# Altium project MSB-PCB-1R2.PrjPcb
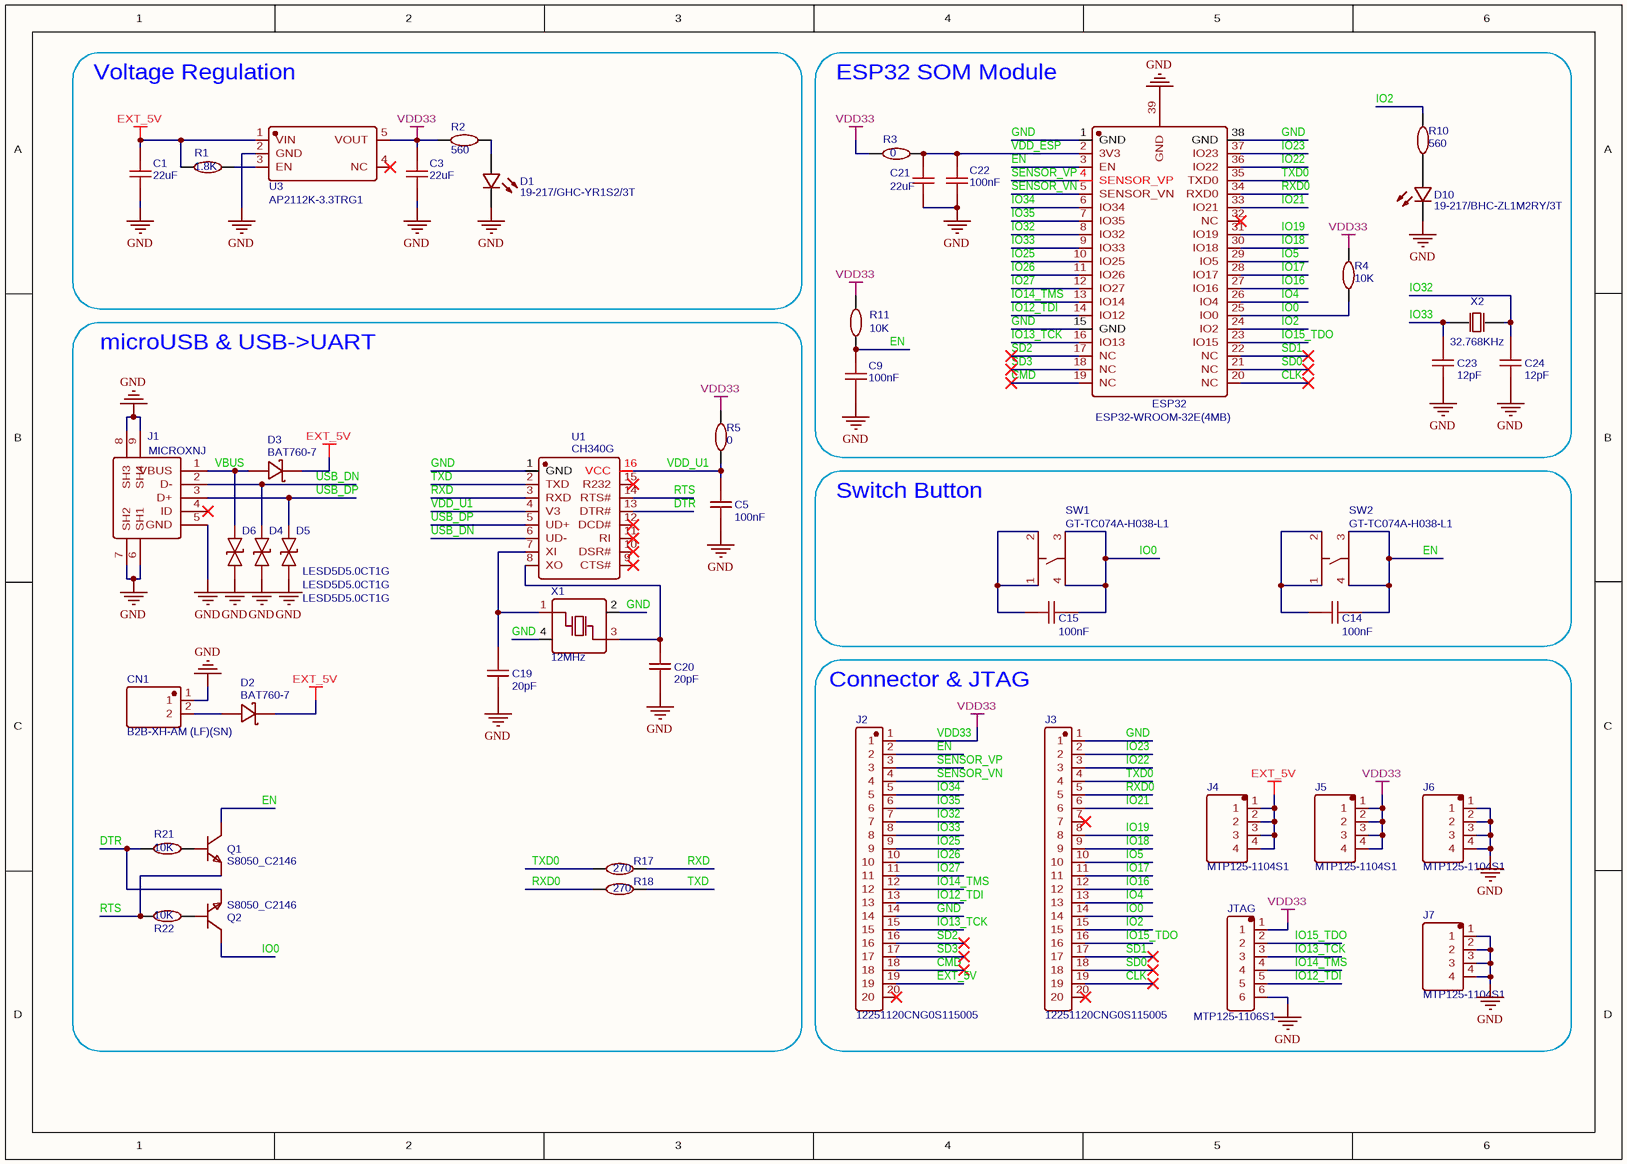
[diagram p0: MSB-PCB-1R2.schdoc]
PRJ_AssemblyVariantStatus: Prototype; PRJ_CompanySiteName: MakerSpace Bonn e.V.; PRJ_DeveloperDate: 15.06.2021; PRJ_DeveloperName: NEK; PRJ_Layouter: NEK; PRJ_PcbNumber: 01; PRJ_PcbVersion: 01; PRJ_SchematicMainTitle: 1rpc ESP32 Baseboard
1 sheet, 48 parts. Net scope: global (net labels, ports and power ports of the same name join across sheets).
Board file: MSB-PCB-1R2.PcbDoc

## Sheet MSB-PCB-1R2.schdoc
size 304 x 217 mm

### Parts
C1  22uF  [C0603]
C3  22uF  [C0603]
C5  100nF  [C0603]
C9  100nF  [C0603]
C14  100nF  [C0603]
C15  100nF  [C0603]
C19  20pF  [C0603]
C20  20pF  [C0603]
C21  22uF  [C0603]
C22  100nF  [C0603]
C23  12pF  [C0603]
C24  12pF  [C0603]
CN1  B2B-XH-AM (LF)(SN)  [CONN-TH_B2B-XH-AM-LF-SN]
D1  19-217/GHC-YR1S2/3T  [LED0603-R-RD]
D2  BAT760-7  [SOD-323_L1.8-W1.3-LS2.5-RD]
D3  BAT760-7  [SOD-323_L1.8-W1.3-LS2.5-RD]
D4  LESD5D5.0CT1G  [SOD-523_L1.2-W0.8-LS1.6-BI]
D5  LESD5D5.0CT1G  [SOD-523_L1.2-W0.8-LS1.6-BI]
D6  LESD5D5.0CT1G  [SOD-523_L1.2-W0.8-LS1.6-BI]
D10  19-217/BHC-ZL1M2RY/3T  [LED0603-R-RD]
ESP32  ESP32-WROOM-32E(4MB)  [WIFI-SMD_ESP32-WROOM-32E]
J1  MICROXNJ  [MICRO-USB-SMD_MICROXNJ]
J2  12251120CNG0S115005  [HDR-TH_19P-P2.54-V]
J3  12251120CNG0S115005  [HDR-TH_19P-P2.54-V]
J4  MTP125-1104S1  [HDR-TH_4P-P2.54-V]
J5  MTP125-1104S1  [HDR-TH_4P-P2.54-V]
J6  MTP125-1104S1  [HDR-TH_4P-P2.54-V]
J7  MTP125-1104S1  [HDR-TH_4P-P2.54-V]
JTAG  MTP125-1106S1  [HDR-TH_6P-P2.54-V]
Q1  S8050_C2146  [SOT-23-3_L3.0-W1.7-P0.95-LS2.9-BR]
Q2  S8050_C2146  [SOT-23-3_L3.0-W1.7-P0.95-LS2.9-BR]
R1  1.8K  [R0603]
R2  560  [R0603]
R3  0  [R0603]
R4  10K  [R0603]
R5  0  [R0603]
R10  560  [R0603]
R11  10K  [R0603]
R17  270  [R0603]
R18  270  [R0603]
R21  10K  [R0603]
R22  10K  [R0603]
SW1  GT-TC074A-H038-L1  [SW-SMD_4P-L4.5-W4.5-P3.00-LS7.0]
SW2  GT-TC074A-H038-L1  [SW-SMD_4P-L4.5-W4.5-P3.00-LS7.0]
U1  CH340G  [SOIC-16_L9.9-W3.9-P1.27-LS6.0-TL]
U3  AP2112K-3.3TRG1  [SOT-25-5_L3.0-W1.8-P0.95-LS3.0-BR]
X1  12MHz  [OSC-SMD_4P-L3.2-W2.5-BL]
X2  32.768KHz  [OSC-SMD_L3.2-W1.5]

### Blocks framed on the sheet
Voltage Regulation: C1 C3 D1 R1 R2 U3
ESP32 SOM Module: C9 C21-C24 D10 ESP32 R3 R4 R10 R11 X2
microUSB & USB->UART: C5 C19 C20 CN1 D2-D6 J1 Q1 Q2 R5 R17 R18 R21 R22 U1 X1
Switch Button: C14 C15 SW1 SW2
Connector & JTAG: J2-J7 JTAG

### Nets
EXT_5V: C1.2 D2.1 D3.1 J2.19 J4.1 J4.2 J4.3 J4.4 R1.1 U3.1(VIN)
GND: C1.1 C3.1 C5.2 C9.1 C19.1 C20.1 C21.1 C22.1 C23.1 C24.1 CN1.1 D1.2(C) D4.1 D5.1 D6.1 D10.2(C) ESP32.1(GND) ESP32.15(GND) ESP32.38(GND) ESP32.39(GND) J1.5(GND) J1.6(SH1) J1.7(SH2) J1.8(SH3) J1.9(SH4) J2.14 J3.1 J6.1 J6.2 J6.3 J6.4 J7.1 J7.2 J7.3 J7.4 JTAG.6 U1.1(GND) U3.2(GND) X1.2(GND) X1.4(GND)
VDD33: C3.2 J2.1 J5.1 J5.2 J5.3 J5.4 JTAG.1 R2.2 R3.1 R4.2 R5.2 R11.2 U3.5(VOUT)
CLK: ESP32.20(NC) J3.19
CMD: ESP32.19(NC) J2.18
DTR: Q2.2(E) R21.1 U1.13(DTR#)
EN: C9.2 C14.2 ESP32.3(EN) J2.2 Q1.3(C) R11.1 SW2.3 SW2.4
IO0: C15.2 ESP32.25(IO0) J3.14 Q2.3(C) R4.1 SW1.3 SW1.4
IO2: ESP32.24(IO2) J3.15 R10.2
IO4: ESP32.26(IO4) J3.13
IO5: ESP32.29(IO5) J3.10
IO12_TDI: ESP32.14(IO12) J2.13 JTAG.5
IO13_TCK: ESP32.16(IO13) J2.15 JTAG.3
IO14_TMS: ESP32.13(IO14) J2.12 JTAG.4
IO15_TDO: ESP32.23(IO15) J3.16 JTAG.2
IO16: ESP32.27(IO16) J3.12
IO17: ESP32.28(IO17) J3.11
IO18: ESP32.30(IO18) J3.9
IO19: ESP32.31(IO19) J3.8
IO21: ESP32.33(IO21) J3.6
IO22: ESP32.36(IO22) J3.3
IO23: ESP32.37(IO23) J3.2
IO25: ESP32.10(IO25) J2.9
IO26: ESP32.11(IO26) J2.10
IO27: ESP32.12(IO27) J2.11
IO32: C24.2 ESP32.8(IO32) J2.7 X2.2(OSC2)
IO33: C23.2 ESP32.9(IO33) J2.8 X2.1(OSC1)
IO34: ESP32.6(IO34) J2.5
IO35: ESP32.7(IO35) J2.6
RTS: Q1.2(E) R22.1 U1.14(RTS#)
RXD: R17.2 U1.3(RXD)
RXD0: ESP32.34(RXD0) J3.5 R18.1
SD0: ESP32.21(NC) J3.18
SD1: ESP32.22(NC) J3.17
SD2: ESP32.17(NC) J2.16
SD3: ESP32.18(NC) J2.17
SENSOR_VN: ESP32.5(SENSOR_VN) J2.4
SENSOR_VP: ESP32.4(SENSOR_VP) J2.3
TXD: R18.2 U1.2(TXD)
TXD0: ESP32.35(TXD0) J3.4 R17.1
USB_DN: D4.2 J1.2(D-) U1.6(UD-)
USB_DP: D5.2 J1.3(D+) U1.5(UD+)
VBUS: D3.2 D6.2 J1.1(VBUS)
VDD_ESP: C21.2 C22.2 ESP32.2(3V3) R3.2
VDD_U1: C5.1 R5.1 U1.4(V3) U1.16(VCC)
NetC14_1: C14.1 SW2.1 SW2.2
NetC15_1: C15.1 SW1.1 SW1.2
NetC19_2: C19.2 U1.7(XI) X1.1(OSC1)
NetC20_2: C20.2 U1.8(XO) X1.3(OSC2)
NetCN1_2: CN1.2 D2.2
NetD1_1: D1.1(A) R2.1
NetD10_1: D10.1(A) R10.1
NetQ1_1: Q1.1(B) R21.2
NetQ2_1: Q2.1(B) R22.2
NetR1_2: R1.2 U3.3(EN)

Not connected (* = marked no-connect by the designer): ESP32 32(NC)*; J1 4(ID)*; J2 20*; J3 7* 20*; U1 9(CTS#)* 10(DSR#)* 11(RI)* 12(DCD#)* 15(R232)*; U3 4(NC)*

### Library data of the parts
C1 C3 C21 = 22uF: BOM_Manufacturer: Murata Electronics; BOM_Manufacturer Part: GRM188R61A226ME15L; nameAlias: Capacitance; Contributor: LCSC
C5 C9 C14 C15 C22 = 100nF: BOM_Manufacturer: YAGEO; BOM_Manufacturer Part: CC0603KRX7R9BB104; nameAlias: Capacitance; SMT Type: Basic
C19 C20 = 20pF: BOM_Manufacturer: CCTC; BOM_Manufacturer Part: TCC0603COG200J500CT; nameAlias: Capacitance; Contributor: LCSC
C23 C24 = 12pF: BOM_Manufacturer: CCTC; BOM_Manufacturer Part: TCC0603COG120J500CT; nameAlias: Capacitance; Contributor: LCSC
CN1 = B2B-XH-AM (LF)(SN): BOM_Manufacturer: JST Sales America; Contributor: LCSC
D1 = 19-217/GHC-YR1S2/3T: BOM_Manufacturer: EVERLIGHT
D2 D3 = BAT760-7: BOM_Manufacturer: DIODES; Contributor: LCSC
D4-D6 = LESD5D5.0CT1G: BOM_Manufacturer: Leshan Radio; Contributor: LCSC
D10 = 19-217/BHC-ZL1M2RY/3T: BOM_Manufacturer: EVERLIGHT
ESP32 = ESP32-WROOM-32E(4MB): BOM_Manufacturer: Espressif Systems; Contributor: LCSC; SMT Type: Extend
J1 = MICROXNJ: BOM_Manufacturer: SHOU HAN; Contributor: LCSC
J2 J3 = 12251120CNG0S115005: BOM_Manufacturer: JILN; Contributor: LCSC
J4-J7 = MTP125-1104S1: BOM_Manufacturer: MINTRON; Contributor: LCSC
JTAG = MTP125-1106S1: BOM_Manufacturer: MINTRON; Contributor: LCSC
Q1 Q2 = S8050_C2146: BOM_Manufacturer: CJ; BOM_Manufacturer Part: S8050; SMT Type: Basic
R1 = 1.8K: BOM_Manufacturer: UniOhm; BOM_Manufacturer Part: 0603WAJ0182T5E; nameAlias: Resistance (Ohms)
R2 R10 = 560: BOM_Manufacturer: UniOhm; BOM_Manufacturer Part: 0603WAF5600T5E; nameAlias: Resistance (Ohms)
R3 R5 = 0: BOM_Manufacturer: UniOhm; BOM_Manufacturer Part: 0603WAF0000T5E; nameAlias: Resistance (Ohms); SMT Type: Basic
R4 R11 R21 R22 = 10K: BOM_Manufacturer: UniOhm; BOM_Manufacturer Part: 0603WAJ0103T5E; nameAlias: Resistance (Ohms)
R17 R18 = 270: BOM_Manufacturer: UniOhm; BOM_Manufacturer Part: 0603WAJ0271T5E; nameAlias: Resistance (Ohms)
SW1 SW2 = GT-TC074A-H038-L1: BOM_Manufacturer: G-Switch; Contributor: LCSC
U1 = CH340G: BOM_Manufacturer: WCH; SMT Type: Basic
U3 = AP2112K-3.3TRG1: BOM_Manufacturer: DIODES; Contributor: LCSC; SMT Type: Extend
X1 = 12MHz: BOM_Manufacturer: YXC; BOM_Manufacturer Part: X322512MSB4SI; nameAlias: Frequency; SMT Type: Basic
X2 = 32.768KHz: BOM_Manufacturer: TKD; BOM_Manufacturer Part: SF32K32768D31T-12.5; nameAlias: Frequency; Contributor: LCSC

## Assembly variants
EDI Std Variant: all parts fitted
